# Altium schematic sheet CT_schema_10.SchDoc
size 277 x 170 mm
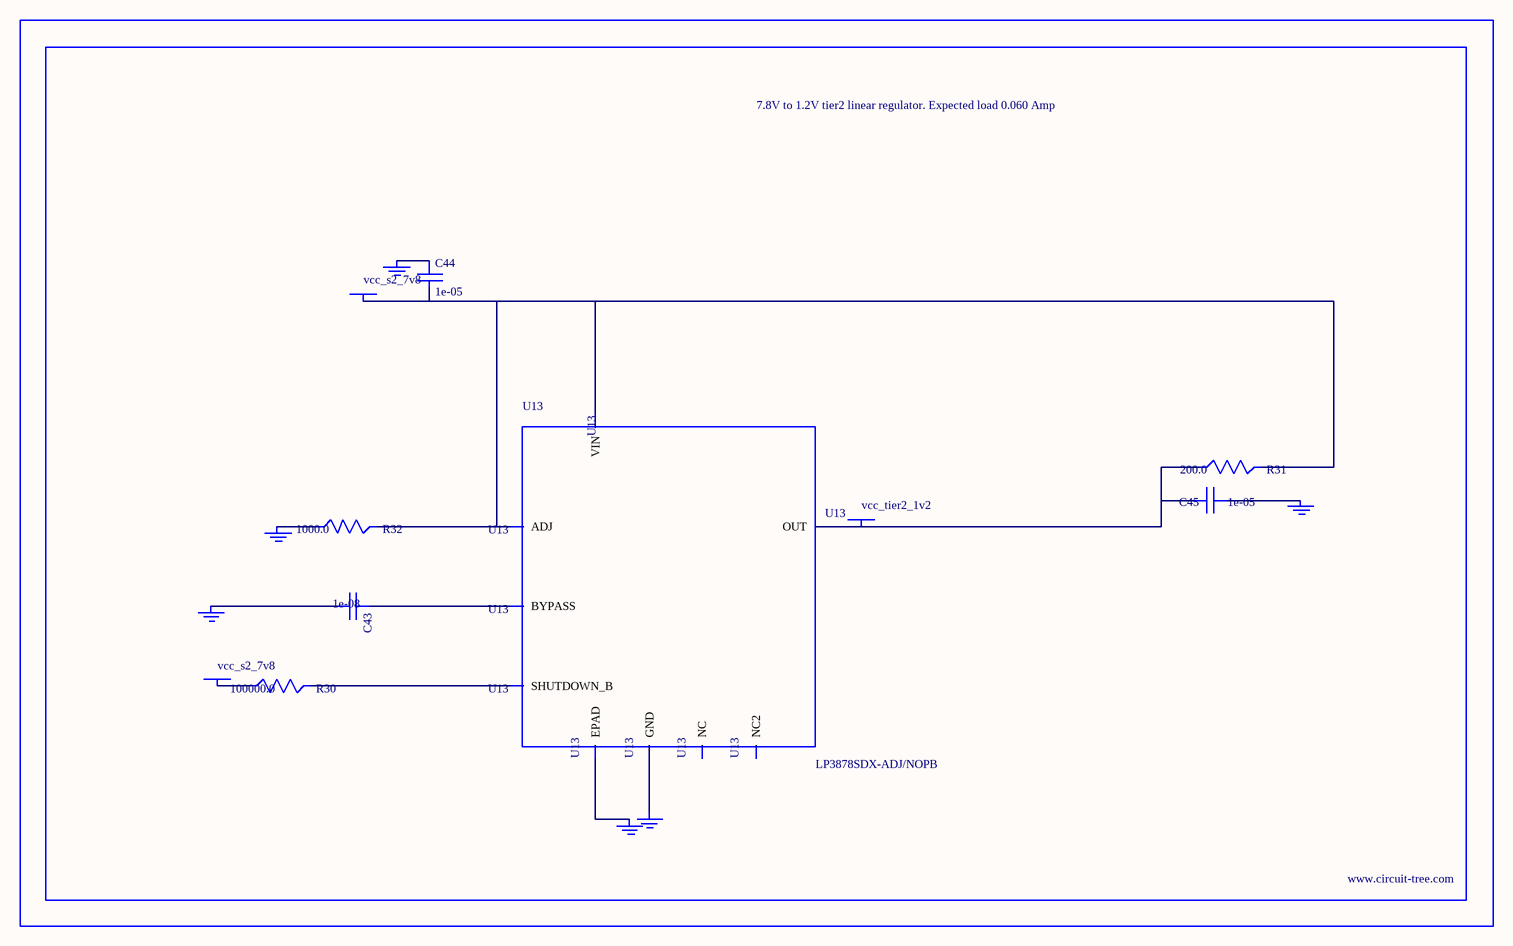
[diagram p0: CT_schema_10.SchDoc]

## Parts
BORDER9  (no value)
C43  1e-08  [C0402]
C44  1e-05  [C1206]
C45  1e-05  [C0805]
GND_INSTANCE_9_0  (no value)
GND_INSTANCE_9_1  (no value)
GND_INSTANCE_9_2  (no value)
GND_INSTANCE_9_3  (no value)
GND_INSTANCE_9_4  (no value)
GND_INSTANCE_9_5  (no value)
POWER_INSTANCE_9_0  vcc_s2_7v8
POWER_INSTANCE_9_1  vcc_s2_7v8
POWER_INSTANCE_9_2  vcc_tier2_1v2
R30  100000.0  [R0603]
R31  200.0  [R0603]
R32  1000.0  [R0603]
U13  LP3878SDX-ADJ/NOPB  [WSON-8]

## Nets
NetC43_1: C43.1 U13.1(BYPASS)
NetC43_2: C43.2 GND_INSTANCE_9_0.0(GND)
NetC44_1: C44.1 GND_INSTANCE_9_1.0(GND)
NetC44_2: C44.2 POWER_INSTANCE_9_0.0(PWR) R31.2 R32.2 U13.4(VIN) U13.6(ADJ)
NetC45_1: C45.1 GND_INSTANCE_9_2.0(GND)
NetC45_2: C45.2 POWER_INSTANCE_9_2.0(PWR) R31.1 U13.5(OUT)
NetGND_INSTANCE_9_3_0: GND_INSTANCE_9_3.0(GND) R32.1
NetGND_INSTANCE_9_4_0: GND_INSTANCE_9_4.0(GND) U13.PAD(EPAD)
NetGND_INSTANCE_9_5_0: GND_INSTANCE_9_5.0(GND) U13.3(GND)
NetPOWER_INSTANCE_9_1_0: POWER_INSTANCE_9_1.0(PWR) R30.1
NetR30_2: R30.2 U13.8(SHUTDOWN_B)

Not connected (* = marked no-connect by the designer): U13 2(NC) 7(NC2)

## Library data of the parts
BORDER9 = BORDER_PAGE9
C43 = C0402C103K3RAC
C44 = C1206C106K3RACTU
C45 = GRM219R60J106ME19D
GND_INSTANCE_9_0-GND_INSTANCE_9_5 = GND
POWER_INSTANCE_9_0-POWER_INSTANCE_9_2 = PWR
R30 = RC0603JR-07100KL
R31 = RC0603JR-07200RL
R32 = RC0603JR-071KL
